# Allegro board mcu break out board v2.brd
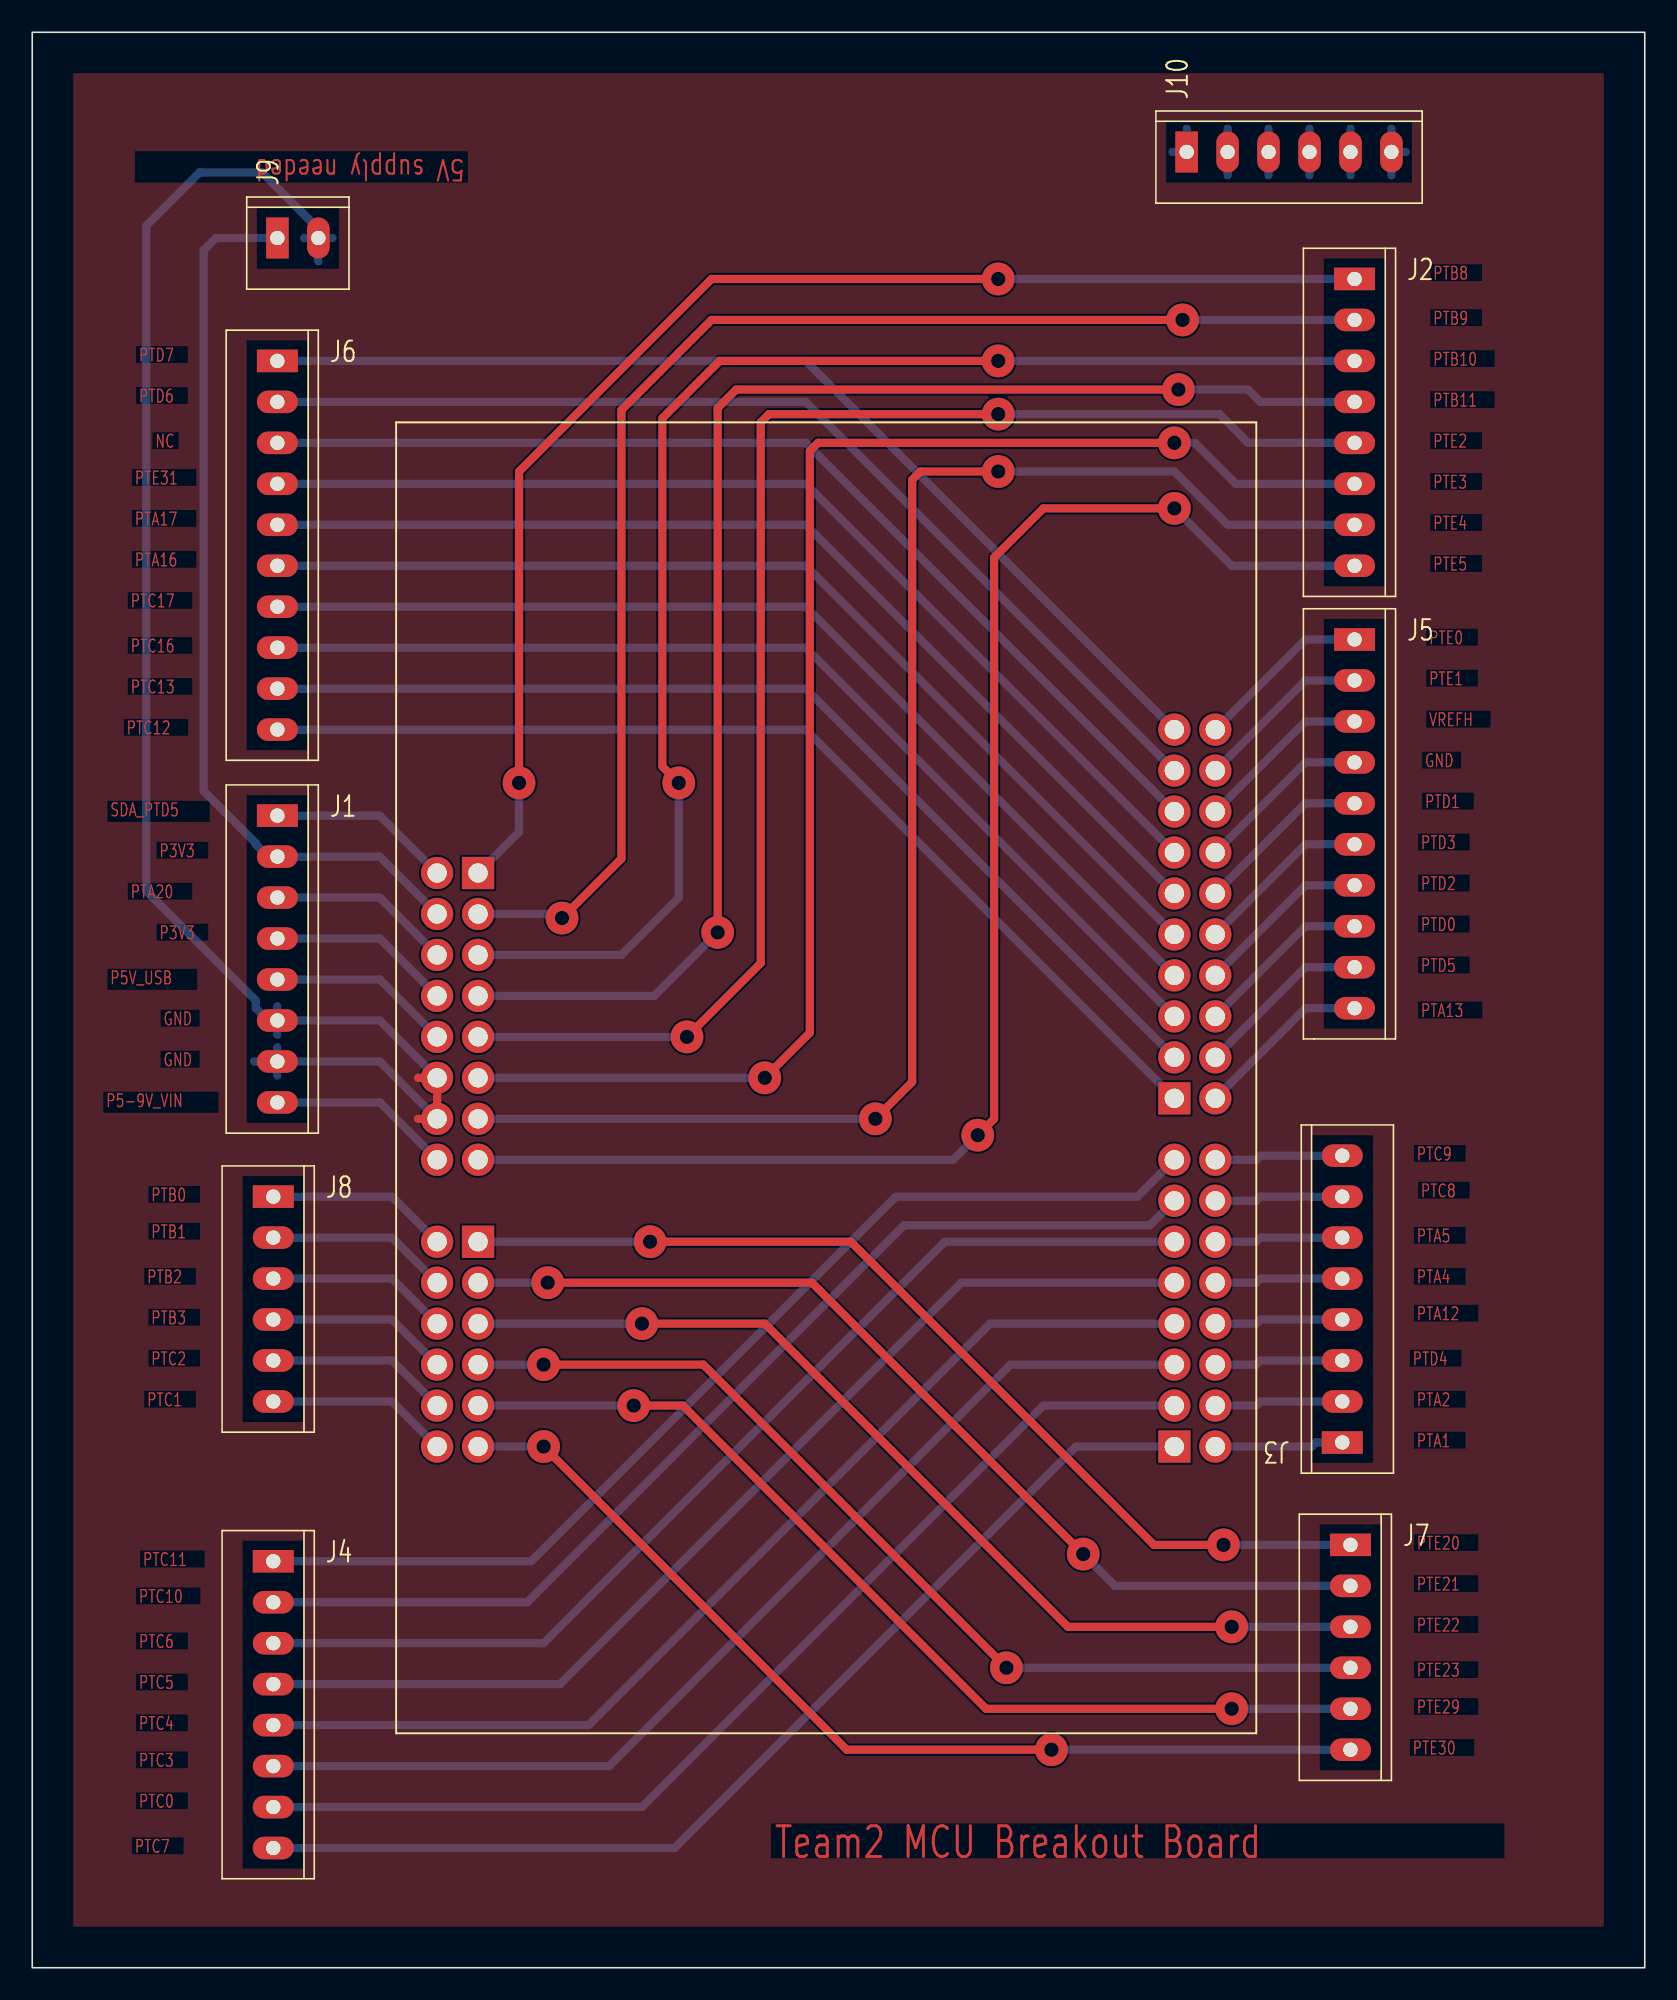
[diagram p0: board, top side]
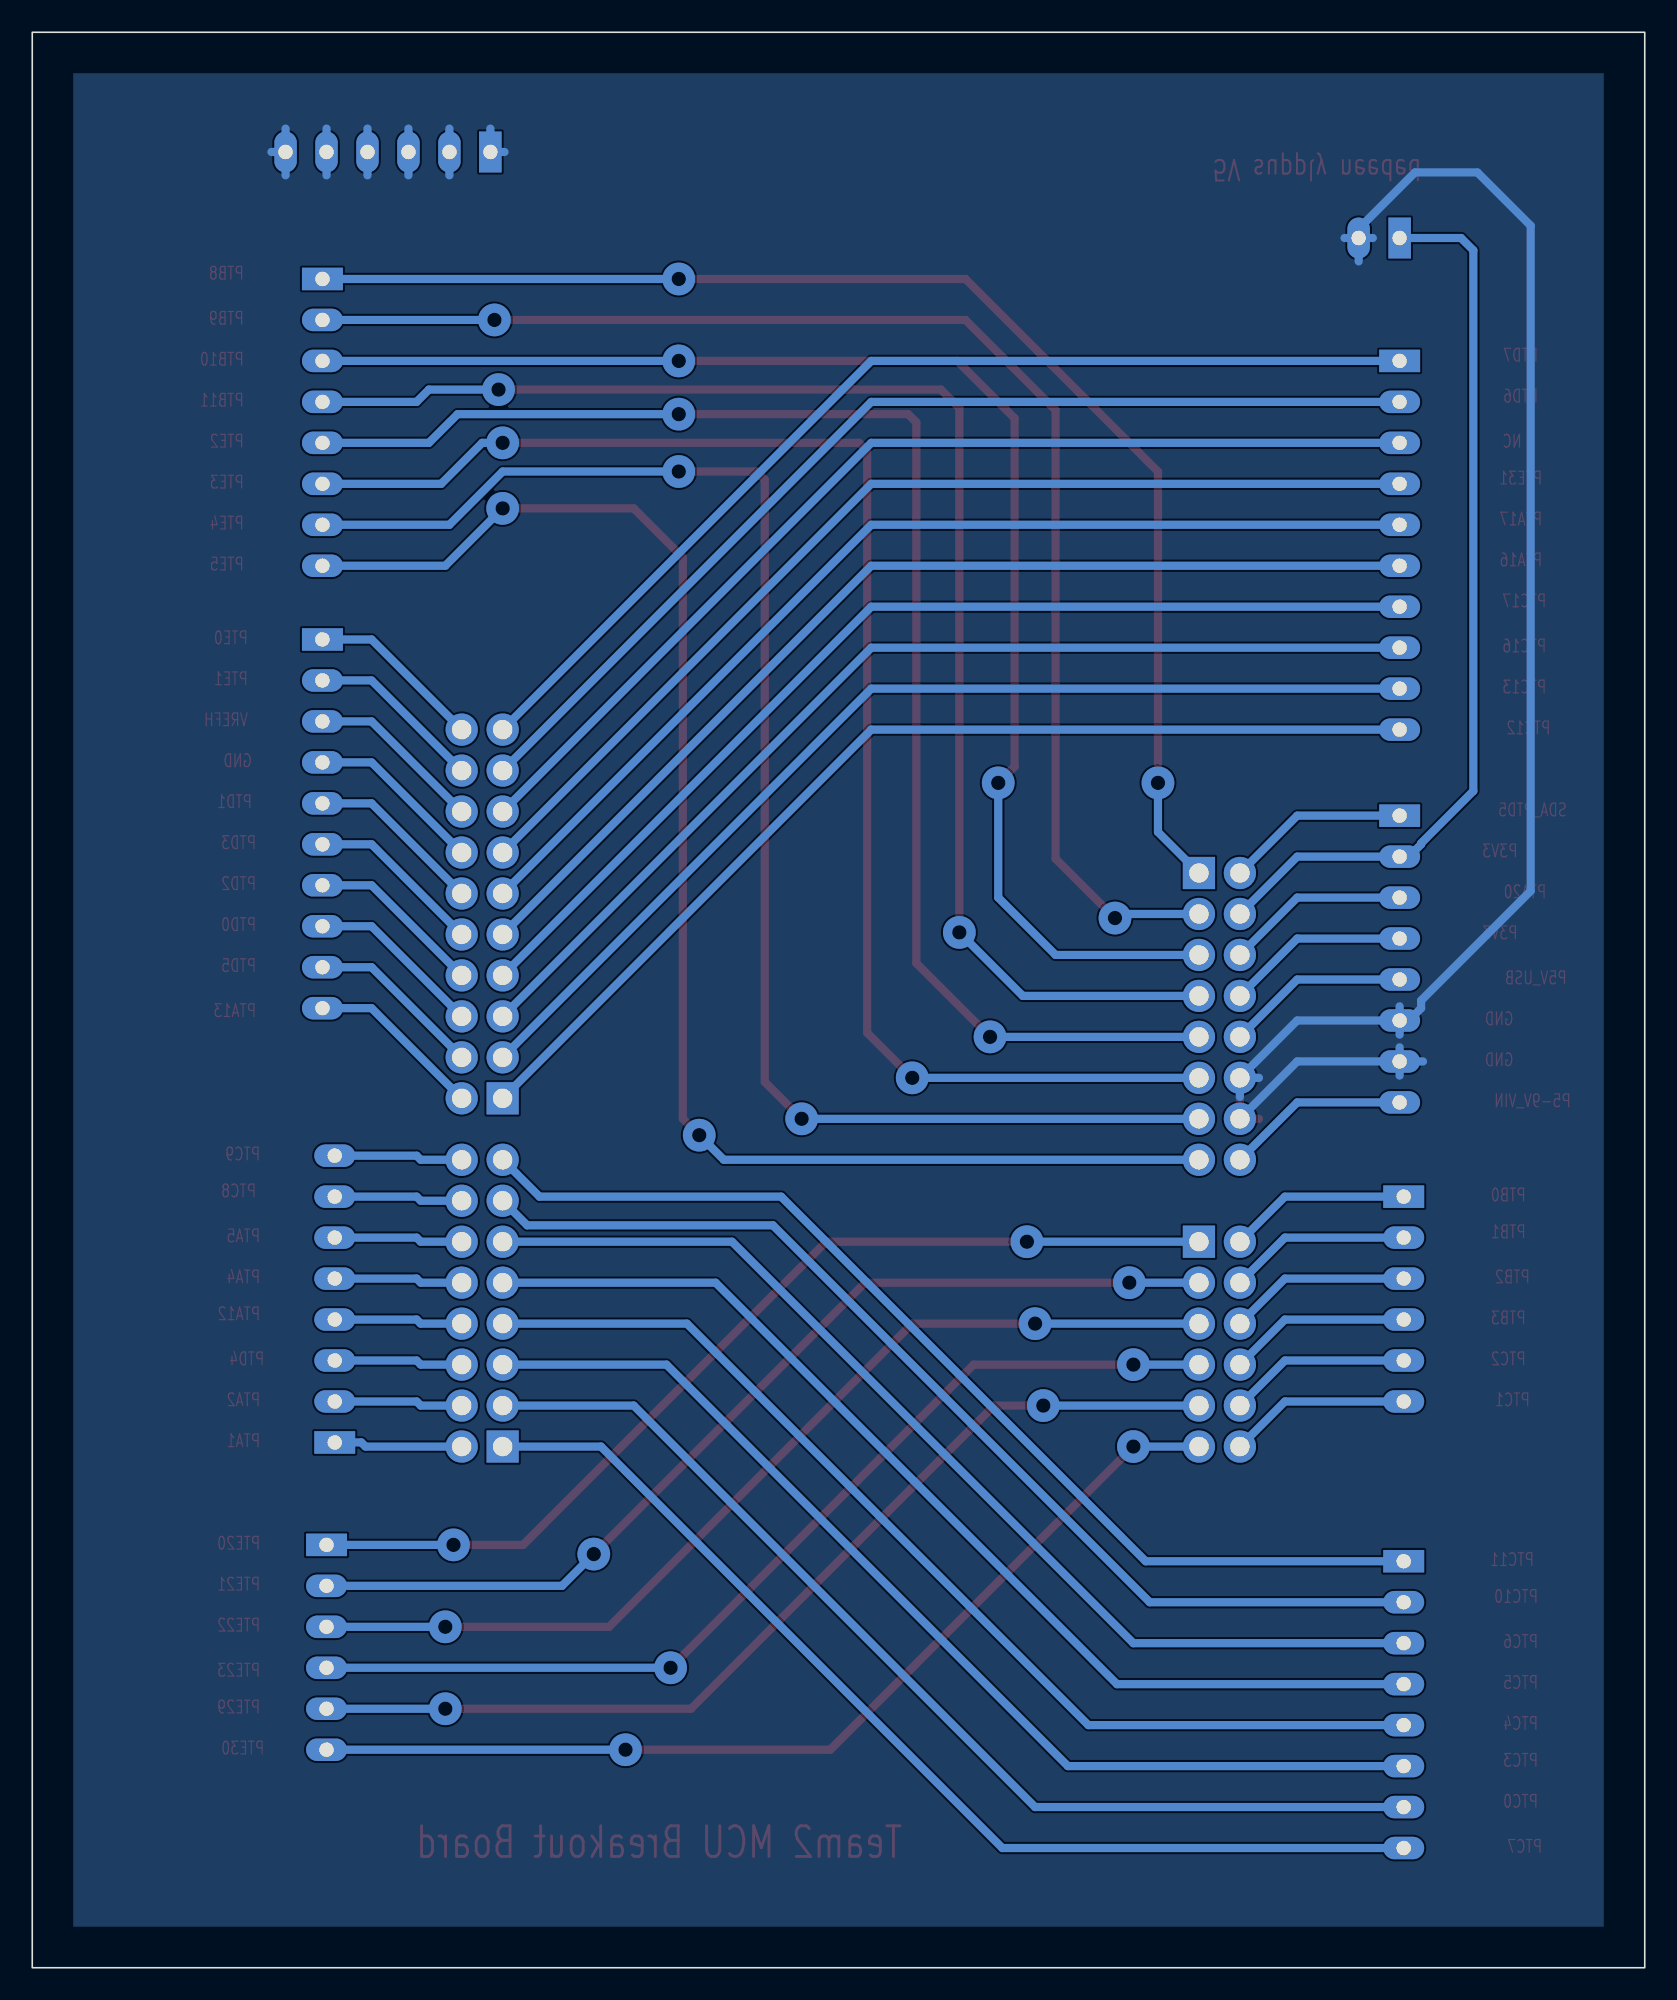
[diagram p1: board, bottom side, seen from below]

Outline 100 x 120 mm; copper layers: TOP, BOTTOM. Coordinates in mm from the lower left corner of the outline.
Outline path: rectangle 0,0 100,120

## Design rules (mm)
constraint set DEFAULT: min track width 0.508

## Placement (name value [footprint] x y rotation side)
J1  CON8  [GU-MOLEX8]  15.2 71.43 0 top
J2  CON8  [GU-MOLEX8]  82 104.7 0 top
J3  CON8  [GU-MOLEX8]  81.24 32.57 180 top
J4  CON8  [GU-MOLEX8]  14.95 25.2 0 top
J5  CON10  [GU-MOLEX10]  82 82.35 0 top
J6  CON10  [GU-MOLEX10]  15.2 99.62 0 top
J7  CON6  [GU-MOLEX6]  81.75 26.22 0 top
J8  CON6  [GU-MOLEX6]  14.95 47.81 0 top
J9  CON2  [GU-MOLEX2]  15.2 107.24 90 top
J10  CON6  [GU-MOLEX6]  71.59 112.58 90 top
U2  FDRM-KL25Z DUAL  [GU-FRDM-KL25Z]  22.57 95.81 270 top

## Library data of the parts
J1-J4 = CON8
J5 J6 = CON10
J7 J8 J10 = CON6
J9 = CON2
U2 = FDRM-KL25Z DUAL

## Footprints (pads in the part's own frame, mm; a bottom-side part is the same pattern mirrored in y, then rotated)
GU-FRDM-KL25Z
  rect 2x2 hole 1.2: J101(63.5,48.26) J201(41.91,48.26) J901(27.94,5.08) J1001(50.8,5.08)
  round 2 hole 1.2: J102(63.5,50.8) J103(60.96,48.26) J104(60.96,50.8) J105(58.42,48.26) J106(58.42,50.8) J107(55.88,48.26) J108(55.88,50.8) J109(53.34,48.26) J110(53.34,50.8) J111(50.8,48.26) J112(50.8,50.8) J113(48.26,48.26) J114(48.26,50.8) J115(45.72,48.26) J116(45.72,50.8) J202(41.91,50.8) J203(39.37,48.26) J204(39.37,50.8) J205(36.83,48.26) J206(36.83,50.8) J207(34.29,48.26) J208(34.29,50.8) J209(31.75,48.26) J210(31.75,50.8) J211(29.21,48.26) J212(29.21,50.8) J213(26.67,48.26) J214(26.67,50.8) J215(24.13,48.26) J216(24.13,50.8) J217(21.59,48.26) J218(21.59,50.8) J219(19.05,48.26) J220(19.05,50.8) J902(27.94,2.54) J903(30.48,5.08) J904(30.48,2.54) J905(33.02,5.08) J906(33.02,2.54) J907(35.56,5.08) J908(35.56,2.54) J909(38.1,5.08) J910(38.1,2.54) J911(40.64,5.08) J912(40.64,2.54) J913(43.18,5.08) J914(43.18,2.54) J915(45.72,5.08) J916(45.72,2.54) J1002(50.8,2.54) J1003(53.34,5.08) J1004(53.34,2.54) J1005(55.88,5.08) J1006(55.88,2.54) J1007(58.42,5.08) J1008(58.42,2.54) J1009(60.96,5.08) J1010(60.96,2.54) J1011(63.5,5.08) J1012(63.5,2.54)
GU-MOLEX2
  rect 2.54x1.397 hole 0.889: 1(0,0)
  oval 2.54x1.397 hole 0.889: 2(0,-2.54)
GU-MOLEX6
  rect 2.54x1.397 hole 0.889: 1(0,0)
  oval 2.54x1.397 hole 0.889: 2(0,-2.54) 3(0,-5.08) 4(0,-7.62) 5(0,-10.16) 6(0,-12.7)
GU-MOLEX8
  rect 2.54x1.397 hole 0.889: 1(0,0)
  oval 2.54x1.397 hole 0.889: 2(0,-2.54) 3(0,-5.08) 4(0,-7.62) 5(0,-10.16) 6(0,-12.7) 7(0,-15.24) 8(0,-17.78)
GU-MOLEX10
  rect 2.54x1.397 hole 0.889: 1(0,0)
  oval 2.54x1.397 hole 0.889: 2(0,-2.54) 3(0,-5.08) 4(0,-7.62) 5(0,-10.16) 6(0,-12.7) 7(0,-15.24) 8(0,-17.78) 9(0,-20.32) 10(0,-22.86)

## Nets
GND: J1.6 J1.7 J9.2 J10.1 J10.2 J10.3 J10.4 J10.5 J10.6 U2.J912 U2.J914
POWER: J1.2 J9.1 U2.J904
N00971: J1.1 U2.J902
N00975: J1.3 U2.J906
N00977: J1.4 U2.J908
N00979: J1.5 U2.J910
N00985: J1.8 U2.J916
N01053: J2.1 U2.J901
N01055: J2.2 U2.J903
N01057: J2.3 U2.J905
N01059: J2.4 U2.J907
N01061: J2.5 U2.J909
N01063: J2.6 U2.J911
N01065: J2.7 U2.J913
N01067: J2.8 U2.J915
N01138: J7.1 U2.J1001
N01140: J7.2 U2.J1003
N01142: J7.3 U2.J1005
N01144: J7.4 U2.J1007
N01146: J7.5 U2.J1009
N01148: J7.6 U2.J1011
N01262: J8.1 U2.J1002
N01268: J8.2 U2.J1004
N01274: J8.3 U2.J1006
N01280: J8.4 U2.J1008
N01286: J8.5 U2.J1010
N01292: J8.6 U2.J1012
N01663: J6.1 U2.J219
N01669: J6.2 U2.J217
N01675: J6.3 U2.J215
N01681: J6.4 U2.J213
N01687: J6.5 U2.J211
N01693: J6.6 U2.J209
N01699: J6.7 U2.J207
N01705: J6.8 U2.J205
N01711: J6.9 U2.J203
N01717: J6.10 U2.J201
N01937: J3.1 U2.J102
N01939: J3.2 U2.J104
N01941: J3.3 U2.J106
N01943: J3.4 U2.J108
N01945: J3.5 U2.J110
N01947: J3.6 U2.J112
N01949: J3.7 U2.J114
N01951: J3.8 U2.J116
N03369: J5.1 U2.J220
N03375: J5.2 U2.J218
N03381: J5.3 U2.J216(VREFH)
N03387: J5.4 U2.J214
N03393: J5.5 U2.J212
N03399: J5.6 U2.J210
N03405: J5.7 U2.J208
N03411: J5.8 U2.J206
N03417: J5.9 U2.J204
N03423: J5.10 U2.J202
N04658: J4.1 U2.J115
N04660: J4.2 U2.J113
N04662: J4.3 U2.J111
N04664: J4.4 U2.J109
N04666: J4.5 U2.J107
N04668: J4.6 U2.J105
N04670: J4.7 U2.J103
N04672: J4.8 U2.J101

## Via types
v1: diameter 2.032, hole 0.889, TOP to BOTTOM, 28 vias

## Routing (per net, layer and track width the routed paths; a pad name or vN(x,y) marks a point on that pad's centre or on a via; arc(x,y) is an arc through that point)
GND: length 123.3
  TOP w0.508: 23.93,55.17 U2.J912 25.11,54 ; 23.93,52.63 U2.J914 25.11,53.81
  BOTTOM w0.508: 84.29,111.13 J10.6 ; J10.6 85.17,112.58 ; J10.6 84.29,114.03 ; 76.67,111.13 J10.3 76.67,114.03 ; 71.59,112.01 J10.1 ; J10.1 70.71,112.58 ; J10.1 71.59,114.03 ; 81.75,114.03 J10.5 81.75,111.13 ; J1.7 15.2,57.07 ; J1.7 13.75,56.19 ; J1.7 21.55,56.19 U2.J914 ; J1.7 15.2,55.31 ; 74.13,111.13 J10.2 74.13,114.03 ; 25.11,54 U2.J912 ; U2.J912 23.93,55.17 ; U2.J912 21.55,58.73 J1.6 ; 17.74,105.8 J9.2 ; J9.2 16.87,107.24 ; J9.2 17.74,107.82 14.25,111.31 10.38,111.31 7.07,108.01 7.07,66.76 13.87,59.97 13.87,59.49 14.63,58.73 J1.6 ; J9.2 18.62,107.24 ; J1.6 15.2,59.61 ; J1.6 15.2,57.85 ; 79.21,111.13 J10.4 79.21,114.03
POWER: length 56.1
  BOTTOM w0.508: J9.1 11.39,107.24 10.63,106.48 10.63,72.96 13.87,69.72 13.87,69.65 14.63,68.89 J1.2 21.55,68.89 U2.J904
N00971: length 11.4
  BOTTOM w0.508: J1.1 21.55,71.43 U2.J902
N00975: length 11.4
  BOTTOM w0.508: J1.3 21.55,66.35 U2.J906
N00977: length 11.4
  BOTTOM w0.508: J1.4 21.55,63.81 U2.J908
N00979: length 11.4
  BOTTOM w0.508: U2.J910 21.55,61.27 J1.5
N00985: length 11.4
  BOTTOM w0.508: U2.J916 21.55,53.65 J1.8
N01053: length 82.7
  TOP w0.508: v1(59.91,104.7) 42.13,104.7 30.19,92.77 v1(30.19,73.46)
  BOTTOM w0.508: U2.J901 30.19,70.41 v1(30.19,73.46) ; v1(59.91,104.7) J2.1
N01055: length 86.1
  TOP w0.508: v1(32.85,65.08) 36.54,68.76 36.54,96.58 42.13,102.16 v1(71.34,102.16)
  BOTTOM w0.508: v1(32.85,65.08) 32.6,65.33 U2.J903 ; v1(71.34,102.16) J2.2
N01057: length 88.5
  TOP w0.508: v1(59.91,99.62) 42.63,99.62 39.08,96.07 39.08,74.48 v1(40.09,73.46)
  BOTTOM w0.508: v1(59.91,99.62) J2.3 ; v1(40.09,73.46) 40.09,66.35 36.54,62.79 U2.J905
N01059: length 89.3
  TOP w0.508: v1(71.08,97.85) 43.65,97.85 42.51,96.7 v1(42.51,64.19)
  BOTTOM w0.508: v1(71.08,97.85) 75.4,97.85 76.16,97.08 J2.4 ; U2.J907 38.57,60.25 v1(42.51,64.19)
N01061: length 90.7
  TOP w0.508: v1(59.91,96.32) 45.68,96.32 45.17,95.81 45.17,62.29 v1(40.6,57.71)
  BOTTOM w0.508: v1(59.91,96.32) 73.62,96.32 75.4,94.54 J2.5 ; U2.J909 v1(40.6,57.71)
N01063: length 92.8
  TOP w0.508: v1(70.83,94.54) 48.73,94.54 48.22,94.04 48.22,57.97 v1(45.43,55.17)
  BOTTOM w0.508: J2.6 74.64,92 72.1,94.54 v1(70.83,94.54) ; v1(45.43,55.17) U2.J911
N01065: length 94.2
  TOP w0.508: v1(59.91,92.77) 55.08,92.77 54.57,92.26 54.57,54.92 v1(52.29,52.63)
  BOTTOM w0.508: J2.7 74.13,89.46 70.83,92.77 v1(59.91,92.77) ; U2.J913 v1(52.29,52.63)
N01067: length 92.9
  TOP w0.508: v1(70.83,90.48) 62.7,90.48 59.65,87.43 59.65,52.63 v1(58.64,51.62)
  BOTTOM w0.508: U2.J915 57.11,50.09 v1(58.64,51.62) ; v1(70.83,90.48) 74.38,86.92 J2.8
N01138: length 61.9
  TOP w0.508: v1(73.88,26.22) 69.56,26.22 50.76,45.01 v1(38.32,45.01)
  BOTTOM w0.508: v1(73.88,26.22) J7.1 ; U2.J1001 v1(38.32,45.01)
N01140: length 61.9
  TOP w0.508: v1(31.97,42.47) 48.35,42.47 v1(65.18,25.65)
  BOTTOM w0.508: U2.J1003 v1(31.97,42.47) ; v1(65.18,25.65) 67.14,23.68 J7.2
N01142: length 61.9
  TOP w0.508: v1(37.81,39.93) 45.43,39.93 64.22,21.14 v1(74.38,21.14)
  BOTTOM w0.508: U2.J1005 v1(37.81,39.93) ; v1(74.38,21.14) J7.3
N01144: length 61.9
  TOP w0.508: v1(31.71,37.39) 41.62,37.39 v1(60.41,18.6)
  BOTTOM w0.508: v1(60.41,18.6) J7.4 ; U2.J1007 v1(31.71,37.39)
N01146: length 61.9
  TOP w0.508: v1(74.38,16.06) 59.14,16.06 40.35,34.85 v1(37.3,34.85)
  BOTTOM w0.508: v1(74.38,16.06) J7.5 ; U2.J1009 v1(37.3,34.85)
N01148: length 61.9
  TOP w0.508: v1(31.71,32.31) 50.51,13.52 v1(63.21,13.52)
  BOTTOM w0.508: U2.J1011 v1(31.71,32.31) ; v1(63.21,13.52) J7.6
N01262: length 11.3
  BOTTOM w0.508: U2.J1002 22.31,47.81 J8.1
N01268: length 11.3
  BOTTOM w0.508: J8.2 22.31,45.27 U2.J1004
N01274: length 11.3
  BOTTOM w0.508: U2.J1006 22.31,42.73 J8.3
N01280: length 11.3
  BOTTOM w0.508: J8.4 22.31,40.19 U2.J1008
N01286: length 11.3
  BOTTOM w0.508: U2.J1010 22.31,37.65 J8.5
N01292: length 11.3
  BOTTOM w0.508: U2.J1012 22.31,35.11 J8.6
N01663: length 65.1
  BOTTOM w0.508: J6.1 47.97,99.62 U2.J219
N01669: length 65.1
  BOTTOM w0.508: U2.J217 47.97,97.08 J6.2
N01675: length 65.1
  BOTTOM w0.508: U2.J215 47.97,94.54 J6.3
N01681: length 65.1
  BOTTOM w0.508: U2.J213 47.97,92 J6.4
N01687: length 65.1
  BOTTOM w0.508: U2.J211 47.97,89.46 J6.5
N01693: length 65.1
  BOTTOM w0.508: U2.J209 47.97,86.92 J6.6
N01699: length 65.1
  BOTTOM w0.508: U2.J207 47.97,84.38 J6.7
N01705: length 65.1
  BOTTOM w0.508: J6.8 47.97,81.84 U2.J205
N01711: length 65.1
  BOTTOM w0.508: J6.9 47.97,79.3 U2.J203
N01717: length 65.1
  BOTTOM w0.508: J6.10 47.97,76.76 U2.J201
N01937: length 8
  BOTTOM w0.508: U2.J102 79.34,32.31 79.59,32.57 J3.1
N01939: length 8
  BOTTOM w0.508: J3.2 76.16,35.11 75.91,34.85 U2.J104
N01941: length 8
  BOTTOM w0.508: J3.3 76.16,37.65 75.91,37.39 U2.J106
N01943: length 8
  BOTTOM w0.508: U2.J108 75.91,39.93 76.16,40.19 J3.4
N01945: length 8
  BOTTOM w0.508: U2.J110 75.91,42.47 76.16,42.73 J3.5
N01947: length 8
  BOTTOM w0.508: J3.6 76.16,45.27 75.91,45.01 U2.J112
N01949: length 8
  BOTTOM w0.508: U2.J114 75.91,47.55 76.16,47.81 J3.7
N01951: length 8
  BOTTOM w0.508: J3.8 76.16,50.35 75.91,50.09 U2.J116
N03369: length 11
  BOTTOM w0.508: U2.J220 78.96,82.35 J5.1
N03375: length 11
  BOTTOM w0.508: U2.J218 78.96,79.81 J5.2
N03381: length 11
  BOTTOM w0.508: U2.J216 78.96,77.27 J5.3
N03387: length 11
  BOTTOM w0.508: U2.J214 78.96,74.73 J5.4
N03393: length 11
  BOTTOM w0.508: J5.5 78.96,72.19 U2.J212
N03399: length 11
  BOTTOM w0.508: J5.6 78.96,69.65 U2.J210
N03405: length 11
  BOTTOM w0.508: J5.7 78.96,67.11 U2.J208
N03411: length 11
  BOTTOM w0.508: U2.J206 78.96,64.57 J5.8
N03417: length 11
  BOTTOM w0.508: U2.J204 78.96,62.03 J5.9
N03423: length 11
  BOTTOM w0.508: U2.J202 78.96,59.49 J5.10
N04658: length 66.2
  BOTTOM w0.508: U2.J115 68.54,47.81 53.56,47.81 30.95,25.2 J4.1
N04660: length 66.2
  BOTTOM w0.508: J4.2 30.7,22.66 54.06,46.03 69.3,46.03 U2.J113
N04662: length 66.2
  BOTTOM w0.508: J4.3 31.71,20.12 56.6,45.01 U2.J111
N04664: length 66.2
  BOTTOM w0.508: J4.4 32.73,17.58 57.62,42.47 U2.J109
N04666: length 66.2
  BOTTOM w0.508: U2.J107 59.4,39.93 34.51,15.04 J4.5
N04668: length 66.2
  BOTTOM w0.508: U2.J105 60.67,37.39 35.78,12.5 J4.6
N04670: length 66.2
  BOTTOM w0.508: U2.J103 62.7,34.85 37.81,9.96 J4.7
N04672: length 66.2
  BOTTOM w0.508: U2.J101 64.73,32.31 39.84,7.42 J4.8

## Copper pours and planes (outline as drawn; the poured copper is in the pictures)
GND on TOP, BOTTOM: 2.54,117.46 97.46,117.46 97.46,2.54 2.54,2.54

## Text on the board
TOP: P5-9V_VIN | SDA_PTD5 | P5V_USB | PTC12 | PTC17 | PTC16 | PTC13 | PTA20 | PTE31 | PTA17 | PTA16 | PTC7 | PTD7 | PTD6 | PTC10 | PTC6 | PTC5 | PTC4 | PTC3 | PTC0 | PTC11 | PTB2 | PTC1 | PTB0 | PTB1 | PTB3 | PTC2 | NC | P3V3 | GND | PTD4 | PTE30 | PTC9 | PTA5 | PTA4 | PTA12 | PTA2 | PTA1 | PTE20 | PTE21 | PTE22 | PTE23 | PTE29 | PTD3 | PTD2 | PTD0 | PTD5 | PTA13 | PTC8 | PTD1 | PTE0 | PTE1 | VREFH | PTB8 | PTB9 | PTB10 | PTB11 | PTE2 | PTE3 | PTE4 | PTE5 | 5V supply needed | Team2 MCU Breakout Board
